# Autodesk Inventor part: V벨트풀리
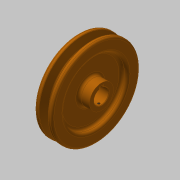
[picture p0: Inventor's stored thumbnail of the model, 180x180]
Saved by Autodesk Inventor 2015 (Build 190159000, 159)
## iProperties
Created: 2015-11
Part Number: V벨트풀리
Material: 강철, 탄소
Document SubType Name: Modeling
Designer: mduedu
Density: 1 g/cm^3
Appearance: 주황색
Author: mduedu
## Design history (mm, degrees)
sketch "스케치1"
  geometry: L1 (-9.5, 0)-(9.5, 0); L2 (0, 0)-(0, 47.7); L3 (-4.877, 47.7)-(-9.5, 47.7); L4 (-9.5, 47.7)-(-9.5, 0); L5 (0, 38.7)-(-1.953, 38.7); L6 (-1.953, 38.7)-(-4.877, 47.7); L7 (4.877, 47.7)-(9.5, 47.7); L8 (9.5, 47.7)-(9.5, 0); L9 (0, 38.7)-(1.953, 38.7); L10 (1.953, 38.7)-(4.877, 47.7); L11 (-9.5, 45)-(9.5, 45); 3 further points
  constraints: 22 end point, 7 point on line, 4 perpendicular, 3 symmetric about line, 1 coincident, 1 horizontal, 1 horizontal alignment, 1 midpoint, 1 vertical
  dimensions: "d0" = 19 distance of L1.start L1.end; "d2" = 95.4 diameter of L2.end L1 (derived); "d3" = 36 deg angle of L10 L6; "d4" = 6.3 distance between parallel lines of L11 L9; "d5" = 2.7 distance between parallel lines of L7 L11; "d6" = 8 distance of point (4, 45) point (-4, 45); "d7" = 90 diameter of L11 L1
revolve "회전1" sketch "스케치1" stored, may be unused: angle "d8" = 90 deg
sketch "스케치2"
  geometry: C1 r 34 at (0, 0); C2 r 13 at (0, 0); 1 further point
  constraints: 2 centre point, 2 coincident
  dimensions: "d9" = 68 diameter of C1; "d10" = 26 diameter of C2
extrude "돌출1" cut sketch "스케치2" distance "d11" = 6; taper "d12" = 0 deg
extrude "돌출3" join sketch "스케치2" distance "d37" = 6; taper "d38" = 0 deg
fillet "모깎기1" dims "d13" = 3
fillet "모깎기2" dims "d14" = 3
fillet "모깎기3" dims "d15" = 1, "d16" = 0.5, "d17" = 2
hole "구멍1" diameter "d20" = 16; stored, may be unused: countersink angle "d24" = 90 deg, drill point angle "d26" = 118 deg; dims "d21" = 6, "d22" = 4, "d23" = 2, "d25" = 8, "d53" = 10, "d54" = 10
sketch "스케치3"
  geometry: L1 (-2.5, 0)-(2.5, 0); L2 (2.5, 0)-(2.5, 10.3); L3 (2.5, 10.3)-(-2.5, 10.3); L4 (-2.5, 10.3)-(-2.5, 0); 2 further points
  constraints: 8 end point, 2 parallel, 1 coincident, 1 horizontal, 1 midpoint, 1 perpendicular
  dimensions: "d27" = 5 distance of L2.end L3.end; "d29" = 10.3 distance of L3.end L1.start
extrude "돌출2" cut sketch "스케치3" stored distance "d30" = 6; taper "d31" = 0 deg
node "작업 평면1"
sketch "스케치4"
  geometry: L1 (19, -37)-(19, 37) reference; 2 further points
  constraints: 1 horizontal alignment
  dimensions: "d52" = 22 distance from line of L1 point (-3, 0)
hole "구멍2" sketch "스케치4" at (-3, 0) diameter "d42" = 2.459; stored, may be unused: countersink angle "d46" = 90 deg, drill point angle "d48" = 118 deg; dims "d43" = 6, "d44" = 4, "d45" = 2, "d47" = 8
chamfer "모따기3" distance "d58" = 0.5; stored, may be unused: second distance "d59" = 2, angle "d60" = 45 deg
node "솔리드1"
mirror "대칭1"
